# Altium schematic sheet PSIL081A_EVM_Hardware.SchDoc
size 431 x 279 mm; Date: Not shown in title block; ApprovedBy: Not shown in title block; CheckedBy: Not shown in title block; Author: Not shown in title block; CompanyName: Not shown in title block; Engineer: Not shown in title block; Organization: Not shown in title block; Address1: Not shown in title block; Address2: Not shown in title block; Address3: Not shown in title block; Address4: Not shown in title block; DocumentNumber: 5; Revision: Use project parameter SCH_Rev; SheetNumber: 5; SheetTotal: 5; PageSetup: Record=PageOptions¦CenterHorizontal=True¦CenterVertical=True¦PrintScale=1.00¦XCorrection=1.00¦YCorrection=1.00¦PrintKind=0¦BorderSize=5000000¦LeftOffset=0¦BottomOffset=0¦Orientation=2¦PaperLength=1000¦PaperWidth=1000¦Scale=100¦PaperSource=15¦PrintQuality=600¦MediaType=1¦DitherType=10¦PaperKind=Letter¦PrintScaleMode=1
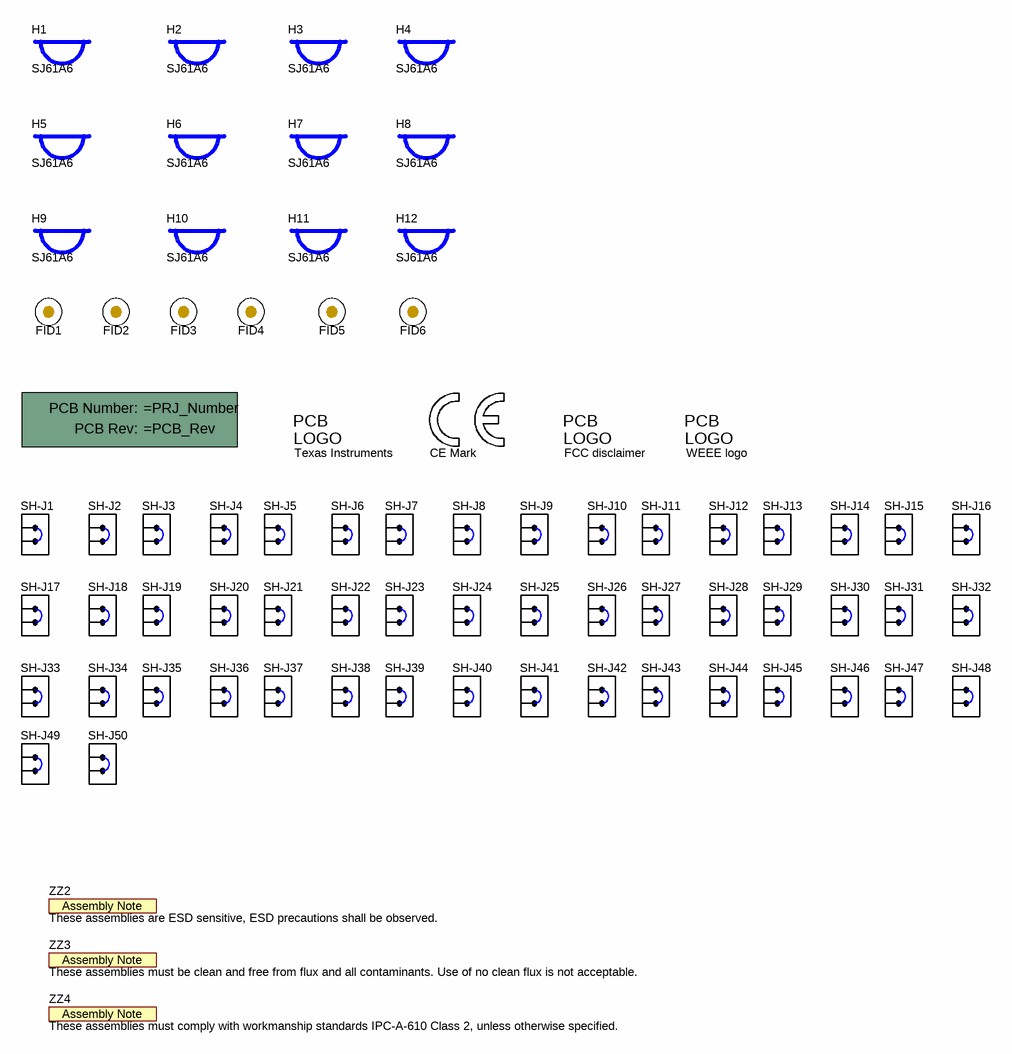
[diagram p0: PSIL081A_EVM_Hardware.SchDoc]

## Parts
!PCB  Printed Circuit Board  (value not drawn)  (mechanical)
FID1  Fiducial  [Fiducial10-20]  (value not drawn)
FID2  Fiducial  [Fiducial10-20]  (value not drawn)
FID3  Fiducial  [Fiducial10-20]  (value not drawn)
FID4  Fiducial  [Fiducial10-20]  (value not drawn)
FID5  Fiducial  [Fiducial10-20]  (value not drawn)
FID6  Fiducial  [Fiducial10-20]  (value not drawn)
H1  SJ61A6  [3M_SJ61A6]
H2  SJ61A6  [3M_SJ61A6]
H3  SJ61A6  [3M_SJ61A6]
H4  SJ61A6  [3M_SJ61A6]
H5  SJ61A6  [3M_SJ61A6]
H6  SJ61A6  [3M_SJ61A6]
H7  SJ61A6  [3M_SJ61A6]
H8  SJ61A6  [3M_SJ61A6]
H9  SJ61A6  [3M_SJ61A6]
H10  SJ61A6  [3M_SJ61A6]
H11  SJ61A6  [3M_SJ61A6]
H12  SJ61A6  [3M_SJ61A6]
Logo1  Texas Instruments  [TI_Stacked_Overlay_Small]  (no BOM)
Logo2  CE Mark  [CE_Mark_5mm]  (no BOM)
Logo3  FCC disclaimer  [FCC_disclaimer]  (no BOM)
Logo4  WEEE logo  [WEEE_Minimum]  (no BOM)
SH-J1  SPC02SYAN  [SPC02SYAN]  (value not drawn)
SH-J2  SPC02SYAN  [SPC02SYAN]  (value not drawn)
SH-J3  SPC02SYAN  [SPC02SYAN]  (value not drawn)
SH-J4  SPC02SYAN  [SPC02SYAN]  (value not drawn)
SH-J5  SPC02SYAN  [SPC02SYAN]  (value not drawn)
SH-J6  SPC02SYAN  [SPC02SYAN]  (value not drawn)
SH-J7  SPC02SYAN  [SPC02SYAN]  (value not drawn)
SH-J8  SPC02SYAN  [SPC02SYAN]  (value not drawn)
SH-J9  SPC02SYAN  [SPC02SYAN]  (value not drawn)
SH-J10  SPC02SYAN  [SPC02SYAN]  (value not drawn)
SH-J11  SPC02SYAN  [SPC02SYAN]  (value not drawn)
SH-J12  SPC02SYAN  [SPC02SYAN]  (value not drawn)
SH-J13  SPC02SYAN  [SPC02SYAN]  (value not drawn)
SH-J14  SPC02SYAN  [SPC02SYAN]  (value not drawn)
SH-J15  SPC02SYAN  [SPC02SYAN]  (value not drawn)
SH-J16  SPC02SYAN  [SPC02SYAN]  (value not drawn)
SH-J17  SPC02SYAN  [SPC02SYAN]  (value not drawn)
SH-J18  SPC02SYAN  [SPC02SYAN]  (value not drawn)
SH-J19  SPC02SYAN  [SPC02SYAN]  (value not drawn)
SH-J20  SPC02SYAN  [SPC02SYAN]  (value not drawn)
SH-J21  SPC02SYAN  [SPC02SYAN]  (value not drawn)
SH-J22  SPC02SYAN  [SPC02SYAN]  (value not drawn)
SH-J23  SPC02SYAN  [SPC02SYAN]  (value not drawn)
SH-J24  SPC02SYAN  [SPC02SYAN]  (value not drawn)
SH-J25  SPC02SYAN  [SPC02SYAN]  (value not drawn)
SH-J26  SPC02SYAN  [SPC02SYAN]  (value not drawn)
SH-J27  SPC02SYAN  [SPC02SYAN]  (value not drawn)
SH-J28  SPC02SYAN  [SPC02SYAN]  (value not drawn)
SH-J29  SPC02SYAN  [SPC02SYAN]  (value not drawn)
SH-J30  SPC02SYAN  [SPC02SYAN]  (value not drawn)
SH-J31  SPC02SYAN  [SPC02SYAN]  (value not drawn)
SH-J32  SPC02SYAN  [SPC02SYAN]  (value not drawn)
SH-J33  SPC02SYAN  [SPC02SYAN]  (value not drawn)
SH-J34  SPC02SYAN  [SPC02SYAN]  (value not drawn)
SH-J35  SPC02SYAN  [SPC02SYAN]  (value not drawn)
SH-J36  SPC02SYAN  [SPC02SYAN]  (value not drawn)
SH-J37  SPC02SYAN  [SPC02SYAN]  (value not drawn)
SH-J38  SPC02SYAN  [SPC02SYAN]  (value not drawn)
SH-J39  SPC02SYAN  [SPC02SYAN]  (value not drawn)
SH-J40  SPC02SYAN  [SPC02SYAN]  (value not drawn)
SH-J41  SPC02SYAN  [SPC02SYAN]  (value not drawn)
SH-J42  SPC02SYAN  [SPC02SYAN]  (value not drawn)
SH-J43  SPC02SYAN  [SPC02SYAN]  (value not drawn)
SH-J44  SPC02SYAN  [SPC02SYAN]  (value not drawn)
SH-J45  SPC02SYAN  [SPC02SYAN]  (value not drawn)
SH-J46  SPC02SYAN  [SPC02SYAN]  (value not drawn)
SH-J47  SPC02SYAN  [SPC02SYAN]  (value not drawn)
SH-J48  SPC02SYAN  [SPC02SYAN]  (value not drawn)
SH-J49  SPC02SYAN  [SPC02SYAN]  (value not drawn)
SH-J50  SPC02SYAN  [SPC02SYAN]  (value not drawn)
ZZ2  These assemblies are ESD sensitive, ESD precautions shall be observed.  [AssemblyNote]  (no BOM)
ZZ3  These assemblies must be clean and free from flux and all contaminants. Use of no clean flux is not acceptable.  [AssemblyNote]  (no BOM)
ZZ4  These assemblies must comply with workmanship standards IPC-A-610 Class 2, unless otherwise specified.  [AssemblyNote]  (no BOM)

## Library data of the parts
!PCB = CMP-0003618-2: Manufacturer: Any
FID1-FID6 = CMP-0077181-1: Fiducial mark.  There is nothing to buy or mount.
H1-H12 = CMP-0079645-1: Manufacturer: 3M; Green_Lifecycle: Not Set; Green_REACh: Incomplete
Logo1 = CMP-0074838-1: Texas Instrument Corporate Signature; SymbolCreator: a0412235; Lib Reference: TI_Logo; Library Reference: Logo
Logo2 = CMP-0074844-1: SymbolCreator: a0412235
Logo3 = CMP-0074847-1: FCC_disclaimer; Library Reference: Logo
Logo4 = CMP-0074769-1
SH-J1-SH-J50 = CMP-0003642-1: Shunt, 100mil, Flash Gold, Black; Manufacturer: Sullins Connector Solutions; Value: 1x2
ZZ2 = CMP-0077236-1
ZZ3 = CMP-0077237-1
ZZ4 = CMP-0077238-1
